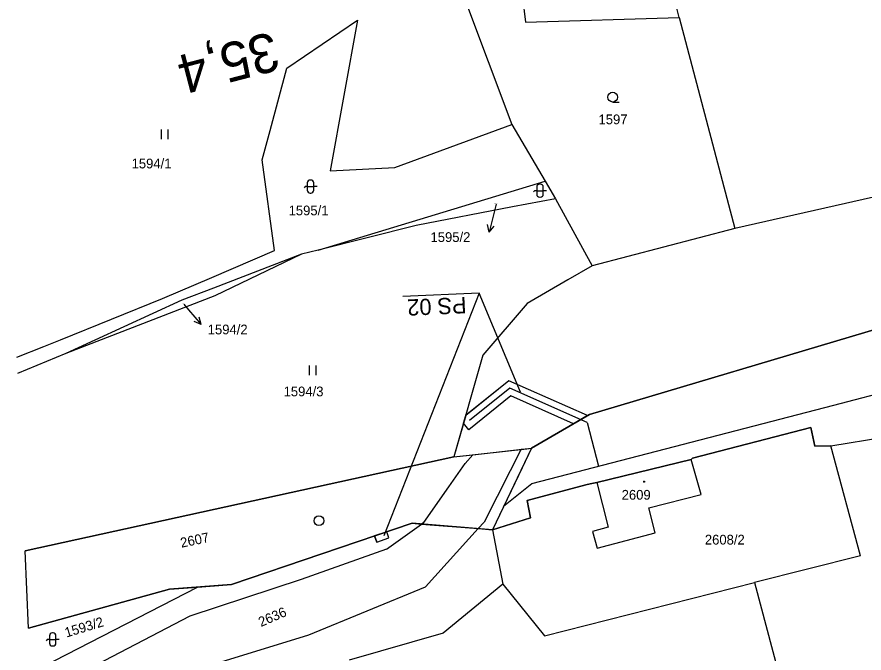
# Model space of a CAD drawing. Extents: x -806456 to -805395, y -1150847 to -1150506.
# Drawn here: x -806240.2 to -806109.9, y -1150734.5 to -1150636.7 of the extents above; entities that cross this region are included whole.
import ezdxf

# ---------------------------------------------------------------- set-up
doc = ezdxf.new("R2010")
doc.units = 0
for name, color, linetype in [('Default', 7, 'Continuous'), ('kilometráž - vrstava 7', 7, 'Continuous'), ('kn_celek - Cisla parcel pomocna', 7, 'Continuous'), ('kn_celek - Cisla pozemkovych parcel', 7, 'Continuous'), ('kn_celek - Cisla stavebnich parcel', 7, 'Continuous'), ('kn_celek - Hranice parcel', 7, 'Continuous'), ('kn_celek - Vnitrni kresby', 7, 'Continuous'), ('kn_celek - Znacky budov', 7, 'Continuous'), ('kn_celek - Znacky kultur', 7, 'Continuous'), ('plochy - DZ_ostat', 7, 'Continuous'), ('plochy - SZDC', 7, 'Continuous'), ('plochy - VB', 7, 'Continuous'), ('PSR_C2_2_trasa_Vimperk - Kabelová trasa', 7, 'Continuous'), ('SOPS', 7, 'Continuous')]:
    doc.layers.add(name, color=color, linetype=linetype)

# ---------------------------------------------------------------- blocks, each defined once
blk = doc.blocks.new('304')
at = {"layer": 'Default'}
blk.add_line((-0.1, 0), (9.9, 0), dxfattribs=at)
blk.add_circle((-0.1, 7.5), 7.5, dxfattribs=at)
blk = doc.blocks.new('316')
at = {"layer": 'Default'}
for p, q in [((-5, 15.5), (-5, 4.5)), ((0.5, 20), (-0.5, 20)), ((5, 4.5), (5, 15.5)), ((-8.3, 10), (-10, 8.1)), ((-5, 10), (-8.3, 10)), ((-5, 10), (5, 10)), ((-0.5, 0), (0.5, 0)), ((10, 10), (5, 10))]:
    blk.add_line(p, q, dxfattribs=at)
for centre, start, end in [((-0.5, 15.5), 90, 180), ((0.5, 15.5), 0, 90), ((-0.5, 4.5), 180, 270), ((0.5, 4.5), 270, 0)]:
    blk.add_arc(centre, 4.5, start, end, dxfattribs=at)
blk = doc.blocks.new('306')
at = {"layer": 'Default'}
for p, q in [((-5.2, 0), (-5.2, 15)), ((4.8, 0), (4.8, 15))]:
    blk.add_line(p, q, dxfattribs=at)
blk = doc.blocks.new('402')
at = {"layer": 'Default'}
for p, q in [((-0.8, 0.8), (0.7, 0.8)), ((-0.8, 0.8), (-0.8, -0.7)), ((0.7, 0.8), (0.7, -0.7)), ((0.7, -0.7), (-0.8, -0.7))]:
    blk.add_line(p, q, dxfattribs=at)
blk = doc.blocks.new('Z61')
at = {"layer": 'Default'}
for p, q in [((0, 0), (30, 0)), ((30, 0), (19.2, 5.3)), ((30, 0), (19.2, -5.3))]:
    blk.add_line(p, q, dxfattribs=at)

msp = doc.modelspace()

# ---------------------------------------------------------------- linework, layer by layer
at = {"layer": 'kilometráž - vrstava 7'}
msp.add_circle((-806193.75, -1150714.19), 0.75, dxfattribs=at)
at = {"layer": 'kn_celek - Cisla parcel pomocna'}
for p, q in [((-806166.46, -1150665.51), (-806166.82, -1150666.91)), ((-806214.51, -1150680.9), (-806213.8, -1150681.74))]:
    msp.add_line(p, q, dxfattribs=at)
at = {"layer": 'kn_celek - Hranice parcel'}
for p, q in [((-806138.31, -1150636.79), (-806141.27, -1150625.54)), ((-806162.76, -1150631.39), (-806161.95, -1150637.48)), ((-806171.35, -1150633.83), (-806164.09, -1150653.24)), ((-806198.68, -1150644.55), (-806187.83, -1150637.18)), ((-806187.83, -1150637.18), (-806192.01, -1150660.38)), ((-806161.95, -1150637.48), (-806138.31, -1150636.79)), ((-806138.31, -1150636.79), (-806129.77, -1150669.25)), ((-806201.27, -1150654.18), (-806198.68, -1150644.55)), ((-806202.47, -1150658.65), (-806201.27, -1150654.18)), ((-806182.09, -1150659.83), (-806164.09, -1150653.24)), ((-806164.09, -1150653.24), (-806158.97, -1150661.95)), ((-806200.59, -1150672.61), (-806202.47, -1150658.65)), ((-806192.01, -1150660.38), (-806182.09, -1150659.83)), ((-806193.88, -1150672.57), (-806158.97, -1150661.95)), ((-806158.97, -1150661.95), (-806157.38, -1150664.65)), ((-806098.93, -1150662.23), (-806129.77, -1150669.25)), ((-806157.38, -1150664.65), (-806163.95, -1150665.92)), ((-806157.38, -1150664.65), (-806151.74, -1150674.98)), ((-806163.95, -1150665.92), (-806178.77, -1150668.8)), ((-806178.77, -1150668.8), (-806193.88, -1150672.57)), ((-806129.77, -1150669.25), (-806151.74, -1150674.98)), ((-806210.23, -1150676.76), (-806200.59, -1150672.61)), ((-806193.88, -1150672.57), (-806196.4, -1150673.2)), ((-806196.4, -1150673.2), (-806209.96, -1150678.4)), ((-806196.4, -1150673.2), (-806209.76, -1150679.59)), ((-806151.74, -1150674.98), (-806155.46, -1150677.14)), ((-806217.79, -1150680.01), (-806210.23, -1150676.76)), ((-806155.46, -1150677.14), (-806161.7, -1150680.75)), ((-806209.96, -1150678.4), (-806214.82, -1150680.27)), ((-806233.52, -1150686.34), (-806217.79, -1150680.01)), ((-806209.76, -1150679.59), (-806232.68, -1150688.44)), ((-806214.82, -1150680.27), (-806232.68, -1150688.44)), ((-806161.7, -1150680.75), (-806168.52, -1150688.73)), ((-806152.11, -1150697.83), (-806107.35, -1150684.54)), ((-806236.08, -1150687.38), (-806233.52, -1150686.34)), ((-806240.19, -1150689.05), (-806236.08, -1150687.38)), ((-806232.68, -1150688.44), (-806240.09, -1150691.55)), ((-806168.52, -1150688.73), (-806172.99, -1150704.37)), ((-806161.05, -1150703.03), (-806152.11, -1150697.83)), ((-806118.08, -1150699.83), (-806136.29, -1150704.55)), ((-806117.47, -1150702.7), (-806118.08, -1150699.83)), ((-806114.99, -1150702.66), (-806092.7, -1150699.08)), ((-806170.06, -1150704.04), (-806162.48, -1150703.19)), ((-806161.05, -1150703.03), (-806162.49, -1150706.04)), ((-806162.48, -1150703.19), (-806161.05, -1150703.03)), ((-806114.99, -1150702.66), (-806117.47, -1150702.7)), ((-806110.42, -1150719.56), (-806114.99, -1150702.66)), ((-806172.99, -1150704.37), (-806238.93, -1150718.82)), ((-806172.99, -1150704.37), (-806170.06, -1150704.04)), ((-806136.51, -1150704.75), (-806151.02, -1150708.33)), ((-806136.29, -1150704.55), (-806136.51, -1150704.75)), ((-806134.96, -1150710.17), (-806136.51, -1150704.75)), ((-806162.49, -1150706.04), (-806167.06, -1150715.57)), ((-806152.7, -1150708.67), (-806161.72, -1150711.06)), ((-806152.01, -1150708.53), (-806152.7, -1150708.67)), ((-806151.02, -1150708.33), (-806152.01, -1150708.53)), ((-806151.02, -1150708.33), (-806149.27, -1150715.2)), ((-806143.02, -1150712.18), (-806134.96, -1150710.17)), ((-806161.72, -1150711.06), (-806161.18, -1150713.76)), ((-806142.01, -1150716.03), (-806143.02, -1150712.18)), ((-806161.18, -1150713.76), (-806167.06, -1150715.57)), ((-806207.21, -1150723.98), (-806179.38, -1150714.57)), ((-806179.38, -1150714.57), (-806177.96, -1150714.69)), ((-806177.96, -1150714.69), (-806169.25, -1150715.39)), ((-806169.25, -1150715.39), (-806167.06, -1150715.57)), ((-806167.06, -1150715.57), (-806165.44, -1150723.96)), ((-806149.27, -1150715.2), (-806151.65, -1150715.85)), ((-806151.65, -1150715.85), (-806150.95, -1150718.39)), ((-806150.95, -1150718.39), (-806142.01, -1150716.03)), ((-806110.42, -1150719.56), (-806126.75, -1150723.7)), ((-806238.43, -1150730.72), (-806216.74, -1150724.69)), ((-806238.13, -1150737.6), (-806212.4, -1150724.39)), ((-806216.74, -1150724.69), (-806212.4, -1150724.39)), ((-806212.4, -1150724.39), (-806207.21, -1150723.98)), ((-806165.44, -1150723.96), (-806174.63, -1150731.47)), ((-806165.44, -1150723.96), (-806159.05, -1150731.9)), ((-806159.05, -1150731.9), (-806126.75, -1150723.7)), ((-806126.75, -1150723.7), (-806122.65, -1150739.16)), ((-806174.63, -1150731.47), (-806189.1, -1150735.63))]:
    msp.add_line(p, q, dxfattribs=at)
at = {"layer": 'kn_celek - Vnitrni kresby'}
for p, q in [((-806162.75, -1150703.4), (-806164.34, -1150706.52)), ((-806162.48, -1150703.19), (-806162.75, -1150703.4)), ((-806171.27, -1150705.39), (-806170.06, -1150704.04)), ((-806173.78, -1150708.97), (-806171.27, -1150705.39)), ((-806164.34, -1150706.52), (-806168.35, -1150714.4)), ((-806177.62, -1150714.44), (-806173.78, -1150708.97)), ((-806183.37, -1150718.58), (-806177.96, -1150714.69)), ((-806177.62, -1150714.44), (-806177.96, -1150714.69)), ((-806177.34, -1150724.35), (-806169.25, -1150715.39)), ((-806168.35, -1150714.4), (-806169.25, -1150715.39)), ((-806183.37, -1150718.58), (-806196.49, -1150723.21)), ((-806196.49, -1150723.21), (-806213.61, -1150728.85)), ((-806195.28, -1150731.73), (-806177.34, -1150724.35)), ((-806213.61, -1150728.85), (-806237.97, -1150741.54)), ((-806212.1, -1150736.94), (-806195.28, -1150731.73))]:
    msp.add_line(p, q, dxfattribs=at)
at = {"layer": 'plochy - DZ_ostat'}
for p, q in [((-806171.16, -1150697.98), (-806172.99, -1150704.37)), ((-806161.05, -1150703.03), (-806152.44, -1150698.02)), ((-806170.06, -1150704.04), (-806162.48, -1150703.19)), ((-806162.48, -1150703.19), (-806161.05, -1150703.03)), ((-806172.99, -1150704.37), (-806170.06, -1150704.04)), ((-806184.86, -1150717.48), (-806182.97, -1150716.84)), ((-806184.86, -1150717.48), (-806182.97, -1150716.84)), ((-806184.86, -1150717.48), (-806182.97, -1150716.84)), ((-806182.97, -1150716.84), (-806183.29, -1150715.89)), ((-806182.97, -1150716.84), (-806183.29, -1150715.89)), ((-806182.97, -1150716.84), (-806183.29, -1150715.89))]:
    msp.add_line(p, q, dxfattribs=at)
for points in [[(-806152.44, -1150698.02), (-806164.51, -1150692.65), (-806171.18, -1150697.99)], [(-806152.44, -1150698.02), (-806164.51, -1150692.65), (-806171.16, -1150697.98)], [(-806184.86, -1150717.48), (-806185.18, -1150716.53), (-806183.29, -1150715.89)], [(-806183.29, -1150715.89), (-806185.18, -1150716.53), (-806184.86, -1150717.48)], [(-806183.29, -1150715.89), (-806185.18, -1150716.53), (-806184.86, -1150717.48)]]:
    msp.add_lwpolyline(points, dxfattribs=at)
at = {"layer": 'plochy - SZDC'}
for p, q in [((-806107.35, -1150684.54), (-806152.11, -1150697.83)), ((-806152.11, -1150697.83), (-806161.05, -1150703.03)), ((-806136.29, -1150704.55), (-806118.08, -1150699.83)), ((-806118.08, -1150699.83), (-806117.47, -1150702.7)), ((-806114.99, -1150702.66), (-806092.7, -1150699.08)), ((-806161.05, -1150703.03), (-806162.49, -1150706.04)), ((-806117.47, -1150702.7), (-806114.99, -1150702.66)), ((-806151.02, -1150708.33), (-806136.51, -1150704.75)), ((-806136.51, -1150704.75), (-806136.29, -1150704.55)), ((-806162.49, -1150706.04), (-806167.06, -1150715.57)), ((-806161.72, -1150711.06), (-806152.7, -1150708.67)), ((-806152.7, -1150708.67), (-806152.01, -1150708.53)), ((-806152.01, -1150708.53), (-806151.02, -1150708.33)), ((-806161.18, -1150713.76), (-806161.72, -1150711.06)), ((-806167.06, -1150715.57), (-806161.18, -1150713.76)), ((-806238.43, -1150730.72), (-806238.93, -1150718.82))]:
    msp.add_line(p, q, dxfattribs=at)
msp.add_lwpolyline([(-806167.06, -1150715.57), (-806179.38, -1150714.57), (-806207.21, -1150723.98), (-806216.74, -1150724.69), (-806238.43, -1150730.72), (-806238.93, -1150718.82), (-806172.99, -1150704.37), (-806161.77, -1150703.11), (-806161.05, -1150703.03)], close=True, dxfattribs=at)
at = {"layer": 'plochy - VB'}
msp.add_line((-806185.18, -1150716.53), (-806183.29, -1150715.89), dxfattribs=at)
for points in [[(-806152.44, -1150698.02), (-806164.51, -1150692.65), (-806171.16, -1150697.98)], [(-806152.44, -1150698.02), (-806154.58, -1150699.26), (-806164.21, -1150694.97), (-806170.71, -1150700.18), (-806171.51, -1150699.19), (-806171.16, -1150697.98)], [(-806185.18, -1150716.53), (-806184.86, -1150717.48), (-806182.97, -1150716.84), (-806183.29, -1150715.89)]]:
    msp.add_lwpolyline(points, dxfattribs=at)
at = {"layer": 'PSR_C2_2_trasa_Vimperk - Kabelová trasa'}
msp.add_line((-806152.51, -1150699.09), (-806150.76, -1150705.8), dxfattribs=at)
for points in [[(-806165.37, -1150711.96), (-806160.98, -1150708.44), (-806114.54, -1150696.43), (-806094.98, -1150691.3), (-806094.7, -1150692.45)], [(-806152.51, -1150699.09), (-806164.36, -1150693.81), (-806170.56, -1150698.78)]]:
    msp.add_lwpolyline(points, dxfattribs=at)
at = {"layer": 'SOPS'}
msp.add_line((-806169.08, -1150679.17), (-806183.77, -1150716.52), dxfattribs=at)
msp.add_lwpolyline([(-806162.75, -1150694.42), (-806169.08, -1150679.17), (-806180.83, -1150679.67)], dxfattribs=at)

# ---------------------------------------------------------------- block references
at = {"layer": 'kn_celek - Cisla parcel pomocna'}
for p, xscale, yscale, rotation in [((-806166.82, -1150666.91), 0.09999999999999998, 0.1, -104.59908), ((-806213.8, -1150681.74), 0.10000000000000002, 0.10000000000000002, -49.550309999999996)]:
    msp.add_blockref('Z61', p, dxfattribs=dict(at, xscale=xscale, yscale=yscale, rotation=rotation))
at = {"layer": 'kn_celek - Znacky budov', "xscale": 0.1, "yscale": 0.10000000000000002}
msp.add_blockref('402', (-806143.73, -1150708.16), dxfattribs=at)
at = {"layer": 'kn_celek - Znacky kultur', "xscale": 0.1, "yscale": 0.10000000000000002}
for name, p in [('304', (-806148.55, -1150649.78)), ('306', (-806217.42, -1150655.52)), ('316', (-806195.04, -1150663.78)), ('316', (-806159.74, -1150664.42)), ('306', (-806194.67, -1150691.82)), ('316', (-806234.69, -1150733.45))]:
    msp.add_blockref(name, p, dxfattribs=at)

# ---------------------------------------------------------------- texts
at = {"layer": 'kilometráž - vrstava 7'}
msp.add_text('35,4', height=6, rotation=194.5881, dxfattribs=at).set_placement((-806200.86, -1150638.89))
at = {"layer": 'kn_celek - Cisla parcel pomocna'}
for s, p in [('1595/2', (-806176.58, -1150671.31)), ('1594/2', (-806210.85, -1150685.52))]:
    msp.add_text(s, height=1.5, dxfattribs=at).set_placement(p)
at = {"layer": 'kn_celek - Cisla pozemkovych parcel'}
for s, height, p in [('1597', 1.5, (-806150.74, -1150653.2)), ('1594/1', 1.5, (-806222.56, -1150659.99)), ('1595/1', 1.5, (-806198.41, -1150667.21)), ('1595/2', 0.1, (-806166.73, -1150665.48)), ('1594/2', 0.1, (-806214.78, -1150680.87)), ('1594/3', 1.5, (-806199.18, -1150695.05)), ('2608/2', 1.5, (-806134.38, -1150717.85))]:
    msp.add_text(s, height=height, dxfattribs=at).set_placement(p)
for s, rotation, p in [('2607', 11.7, (-806214.89, -1150718.34)), ('2636', 23.4, (-806202.66, -1150730.54)), ('1593/2', 16.887, (-806232.59, -1150732.16))]:
    msp.add_text(s, height=1.5, rotation=rotation, dxfattribs=at).set_placement(p)
at = {"layer": 'kn_celek - Cisla stavebnich parcel'}
msp.add_text('2609', height=1.5, dxfattribs=at).set_placement((-806147.18, -1150710.95))
at = {"layer": 'SOPS'}
msp.add_text('PS 02', height=2.5, rotation=182.4308, dxfattribs=at).set_placement((-806171.1, -1150679.77))

doc.saveas('drawing.dxf')
